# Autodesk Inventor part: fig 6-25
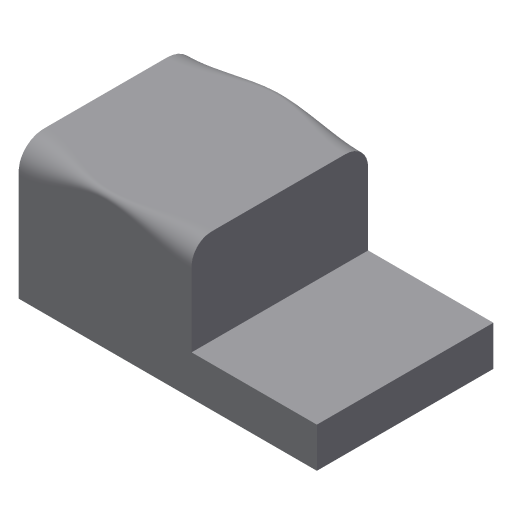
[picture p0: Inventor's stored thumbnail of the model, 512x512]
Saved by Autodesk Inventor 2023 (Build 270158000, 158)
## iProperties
Created: 2004-05
Part Number: fig 6-25
Document SubType Name: Modeling
Designer: CADCIM Technologies
Manufacturer: Standard
Standards Organization: Custom
Density: 1 g/cm^3
Material: Generic
Appearance: Default
Author: CADCIM Technologies
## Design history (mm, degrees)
node "Sketch1"
sketch "Sketch2"
  geometry: L1 (0.098, 47.711)-(0.098, 0.049); L2 (0.098, 0.049)-(-105.483, 0.049); L3 (-105.483, 0.049)-(-105.483, 14.192); L4 (-105.483, 14.192)-(-61.139, 14.192); L5 (-61.139, 14.192)-(-61.139, 47.711); L6 (-61.139, 47.711)-(0.098, 47.711)
  constraints: 12 end point, 3 parallel, 2 perpendicular, 1 vertical
extrude "Extrusion1" new body sketch "Sketch2" stored distance "d0" = 62.5; taper "d1" = 0 deg
fillet "Fillet9" dims "d61" = 10, "d62" = 8, "d63" = 2, "d64" = 5
fillet "Fillet10" dims "d65" = 8, "d66" = 10, "d67" = 2, "d68" = 5
body "Solid1"
